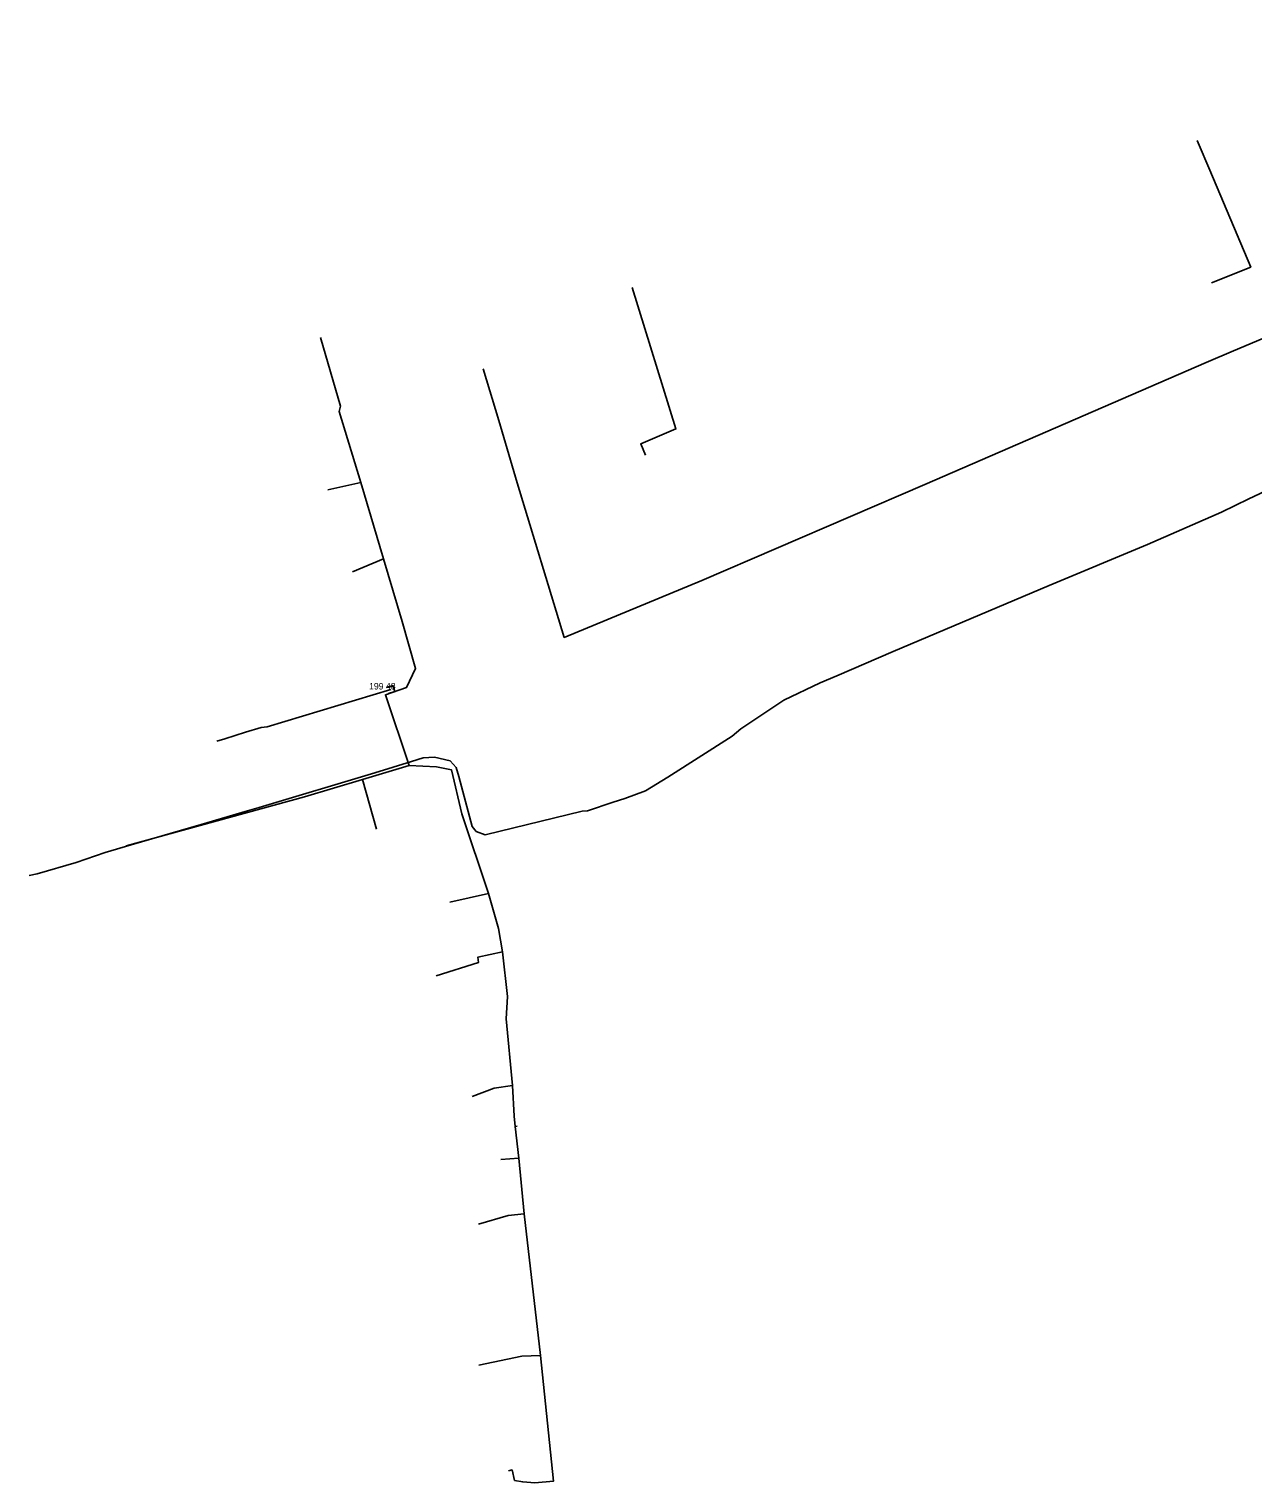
# Model space of a CAD drawing. Extents: x -539701 to -539089, y -1156443 to -1155859.
# Drawn here: x -539701.5 to -539560, y -1156184.5 to -1156016.4 of the extents above; entities that cross this region are included whole.
import ezdxf

# ---------------------------------------------------------------- set-up
doc = ezdxf.new("R2010")
doc.units = 0
for name, color, linetype in [('Vrstva 1', 7, 'Continuous'), ('Vrstva 10', 7, 'Continuous'), ('Vrstva 3', 7, 'Continuous'), ('Vrstva 30', 7, 'Continuous'), ('Vrstva 31', 7, 'Continuous')]:
    doc.layers.add(name, color=color, linetype=linetype)

msp = doc.modelspace()

# ---------------------------------------------------------------- linework, layer by layer
at = {"layer": 'Vrstva 1'}
msp.add_line((-539659.68, -1156092.75), (-539659.68, -1156092.75), dxfattribs=at)
at = {"layer": 'Vrstva 10'}
msp.add_lwpolyline([(-539659.924, -1156093.22), (-539659.21, -1156092.994), (-539659.436, -1156092.28), (-539660.15, -1156092.506)], dxfattribs=at)
at = {"layer": 'Vrstva 30'}
msp.add_lwpolyline([(-539659.676, -1156092.752), (-539673.974, -1156097.052), (-539674.653, -1156097.134), (-539676.443, -1156097.683), (-539677.674, -1156098.054), (-539678.864, -1156098.454), (-539679.783, -1156098.733)], dxfattribs=at)
at = {"layer": 'Vrstva 31'}
for p, q in [((-539647.191, -1156061.661), (-539649.005, -1156055.665)), ((-539663.144, -1156068.82), (-539666.947, -1156069.667)), ((-539662.946, -1156103.165), (-539661.334, -1156108.902)), ((-539648.363, -1156116.353), (-539652.832, -1156117.326)), ((-539646.966, -1156147.109), (-539644.885, -1156146.947))]:
    msp.add_line(p, q, dxfattribs=at)
for points in [[(-539476.28, -1156016.39), (-539477.81, -1156017.03), (-539486.21, -1156020.82), (-539500.43, -1156027.21), (-539535.763, -1156042.208), (-539541.714, -1156044.771), (-539548.99, -1156047.88), (-539558.88, -1156052.16), (-539562.266, -1156053.604), (-539565.457, -1156054.954), (-539597.95, -1156069.03), (-539623.73, -1156080.16), (-539639.622, -1156086.732), (-539645.058, -1156068.843)], [(-539564.819, -1156045.733), (-539560.28, -1156043.91), (-539565.024, -1156032.709), (-539566.37, -1156029.53), (-539566.47, -1156029.287)], [(-539630.223, -1156065.64), (-539630.79, -1156064.33), (-539626.726, -1156062.625), (-539631.789, -1156046.264)], [(-539663.144, -1156068.82), (-539665.635, -1156060.603), (-539665.489, -1156059.973), (-539667.79, -1156052.045)], [(-539645.058, -1156068.843), (-539646.204, -1156064.907), (-539647.191, -1156061.661)], [(-539554.65, -1156068.16), (-539555.49, -1156068.35), (-539560.5, -1156070.7), (-539563.67, -1156072.23), (-539572.23, -1156075.98), (-539583.6, -1156080.73), (-539601.6, -1156088.35), (-539608.14, -1156091.17), (-539610.04, -1156091.99), (-539614.25, -1156093.98), (-539619.23, -1156097.29), (-539620.23, -1156098.13), (-539627.65, -1156102.89)], [(-539663.144, -1156068.82), (-539660.495, -1156077.631), (-539664.088, -1156079.153)], [(-539660.495, -1156077.631), (-539658.345, -1156084.873), (-539656.81, -1156090.312), (-539657.838, -1156092.507), (-539660.299, -1156093.351), (-539657.558, -1156101.556)], [(-539701.47, -1156114.27), (-539700.54, -1156114.06), (-539696.02, -1156112.74), (-539692.66, -1156111.59), (-539689.68, -1156110.72), (-539681.58, -1156108.36), (-539676.23, -1156106.79), (-539674.87, -1156106.4), (-539661.53, -1156102.37), (-539657.26, -1156101.06), (-539655.94, -1156100.67), (-539654.62, -1156100.57), (-539652.82, -1156101.01), (-539652.11, -1156101.78), (-539651.8, -1156102.8), (-539650.28, -1156108.6), (-539649.79, -1156109.16), (-539648.78, -1156109.54), (-539637.55, -1156106.83), (-539636.95, -1156106.78), (-539633.98, -1156105.79), (-539632.61, -1156105.35)], [(-539662.946, -1156103.165), (-539657.558, -1156101.556), (-539654.401, -1156101.697), (-539652.657, -1156102.029), (-539651.472, -1156107.134), (-539648.363, -1156116.353)], [(-539690.248, -1156110.844), (-539669.631, -1156105.162), (-539662.946, -1156103.165)], [(-539627.65, -1156102.89), (-539630.23, -1156104.48), (-539632.61, -1156105.35)], [(-539648.363, -1156116.353), (-539647.213, -1156120.37), (-539646.763, -1156123.081)], [(-539646.763, -1156123.081), (-539649.616, -1156123.71), (-539649.535, -1156124.323), (-539654.419, -1156125.865)], [(-539646.763, -1156123.081), (-539646.195, -1156128.264), (-539646.347, -1156130.839), (-539645.615, -1156138.549)], [(-539645.615, -1156138.549), (-539647.739, -1156138.849), (-539650.249, -1156139.822)], [(-539645.615, -1156138.549), (-539645.408, -1156142.093), (-539645.28, -1156143.275)], [(-539645.073, -1156143.253), (-539645.28, -1156143.275)], [(-539645.073, -1156143.253), (-539645.28, -1156143.275), (-539644.885, -1156146.947)], [(-539645.28, -1156143.275), (-539644.885, -1156146.947)], [(-539644.885, -1156146.947), (-539644.268, -1156153.356)], [(-539644.885, -1156146.947), (-539644.268, -1156153.356), (-539642.383, -1156169.757)], [(-539644.268, -1156153.356), (-539646.12, -1156153.563), (-539649.55, -1156154.579)], [(-539644.268, -1156153.356), (-539642.383, -1156169.757)], [(-539642.383, -1156169.757), (-539644.54, -1156169.844), (-539649.512, -1156170.877)], [(-539642.383, -1156169.757), (-539640.851, -1156184.274), (-539643.012, -1156184.488), (-539644.427, -1156184.38), (-539645.357, -1156184.204), (-539645.652, -1156182.991), (-539646.067, -1156183.103)]]:
    msp.add_lwpolyline(points, dxfattribs=at)

# ---------------------------------------------------------------- texts
at = {"layer": 'Vrstva 3'}
msp.add_text('199 48 ', height=0.75, dxfattribs=at).set_placement((-539662.18, -1156092.75))

doc.saveas('drawing.dxf')
